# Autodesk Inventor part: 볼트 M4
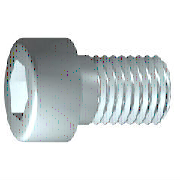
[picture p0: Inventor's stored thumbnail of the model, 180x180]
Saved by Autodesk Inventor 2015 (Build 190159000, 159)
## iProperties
IsCustomPart: 1
Created: 2012-02
Part Number: 볼트 M4
Material: 강철, 연강
Description: 6각머리 태핑 나사
Document SubType Name: Modeling
Standard: KS B 1003
Designer: mduedu
Standards Organization: KS
Language: ko-KR
Size Designation: M 4 x 10
Categories: <MemberInstance><Categories><Category DisplayName="조임쇠" InternalName="e4da775c-781d-43d5-af7c-5136215cf5a6" Mnemonic="FSTN"><Category DisplayName="볼트" InternalN
Density: 7.85 g/cm^3
Appearance: 강철
Mass: 2.03451 g
Surface Area: 3.0572 cm^2
Volume: 0.259174 cm^3
Author: mduedu
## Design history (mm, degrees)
sketch "스케치1"
  geometry: L1 (-1, 0)-(10, 0); L2 (10, 0)-(10, 2); L3 (10, 2)-(1.75, 2); L4 (1.75, 2)-(1.32, 2); L5 (1.32, 2)-(0, 2); L6 (0, 2)-(0, 3.5); L7 (0, 3.5)-(-4, 3.5); L8 (-4, 3.5)-(-4, 1.732); L9 (-4, 1.732)-(-2, 1.732); L10 (-2, 1.732)-(-1, 0); L11 (-6.8, 0)-(12.8, 0) reference; L12 (0, -0.7)-(0, 4.2) reference; L13 (1.75, 2)-(0, 2)
  constraints: 22 end point, 6 parallel, 2 collinear, 2 perpendicular, 1 horizontal, 1 point on line
  dimensions: "d1" = 8.25 distance from line of L3.end L2 (= GEL); "d2" = 0.42952 distance of L4.end L3.end (computed from GAL); "d3" = 4 distance between parallel lines of L8 L6 (= KOH); "d4" = 2 distance of L8.end L9.end (= INTI); "d5" = 60 deg angle of L10 L1; "d6" = 4 diameter of L3 L1 (= GD); "d7" = 4 diameter of L5 L1 (= BDM); "d8" = 3.4641 diameter of L9 L1 (= 1.1547 x SW); "d9" = 7 diameter of L7 L1 (= KOD); "d26" = 10 distance between parallel lines of L12 L2 (= NLG)
revolve "본체" sketch "스케치1" stored, may be unused: angle "d10" = 90 deg
sketch "스케치2"
  geometry: L1 (0, -4.9)-(0, 4.9) reference; L2 (-4.9, 0)-(4.9, 0) reference; L3 (1.732, 0)-(0.866, -1.5); L4 (0.866, -1.5)-(-0.866, -1.5); L5 (-0.866, -1.5)-(-1.732, 0); L6 (-1.732, 0)-(-0.866, 1.5); L7 (-0.866, 1.5)-(0.866, 1.5); L8 (0.866, 1.5)-(1.732, 0); 2 further points
  constraints: 12 end point, 1 coincident, 1 horizontal alignment, 1 point on line, 12 other
extrude "슬롯" join sketch "스케치2" stored distance "d11" = 10; taper "d12" = 0 deg
workplane "Work Plane1"
fillet "Fillet2" dims "d30" = 0.1 (= R)
body "Solid1"
fillet "모깎기1" dims "d17" = 0.4 (= RR)
feature "스레드" dims "d13" = 8.25 (= GEL), "d14" = 0
chamfer "모따기1" distance "d15" = 0.42941 (= -0.5 x SPD + 0.5 x GD); stored, may be unused: second distance "d16" = 0.42941 (= GUL), angle "d27" = 45 deg
other parameters: "GD" = 4 (= NND) [user parameter; used in 2 equation terms], "NLG" = 10 [user parameter; used in 1 equation term], "GEL" = 8.25 [user parameter; used in 2 equation terms], "KOD" = 7 [user parameter; used in 1 equation term], "KOH" = 4 [user parameter; used in 1 equation term], "INTI" = 2 [user parameter; used in 1 equation term], "GAL" = 0.42941 (= 0.61345 x PTC) [user parameter; used in 1 equation term], "GUL" = 0.42941 (= 0.61345 x PTC) [user parameter; used in 1 equation term], "BDM" = 4 (= NND) [user parameter; used in 1 equation term], "SW" = 3 [user parameter; used in 2 equation terms], "RR" = 0.4 [user parameter; used in 1 equation term], "SPD" = 3.14117 (= NND - 1.2269 x PTC) [user parameter; used in 1 equation term], "d19" = 0, "d28" = 0, "d29" = 0, "R" = 0.1 [user parameter; used in 1 equation term], "PHH" = 0.2 [user parameter], "GD1" = 3.14117 (= THREADDIA - 1.2269 x PTC) [user parameter], "THREADDIA" = 4 [user parameter; used in 1 equation term], "FAWI" = 45 deg [user parameter], "TPU" = 14.28571 (computed from PTC) [user parameter], "PTC" = 0.7 [user parameter; used in 5 equation terms], "NND" = 4 [user parameter; used in 3 equation terms], "TOA" = 30 deg [user parameter], "E0" = 3.465 (= 1.155 x SW) [user parameter]
